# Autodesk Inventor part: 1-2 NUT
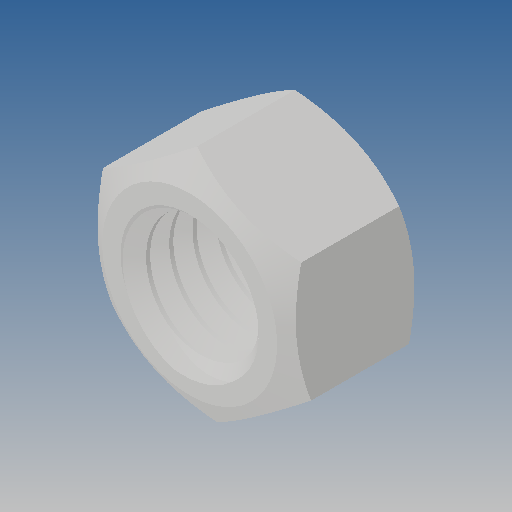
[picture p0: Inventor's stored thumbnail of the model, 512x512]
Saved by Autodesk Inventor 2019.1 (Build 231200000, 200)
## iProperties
Created: 2012-10
Part Number: 1-2 NUT
Material: Ogólny
Document SubType Name: Modeling
Designer: CADENGINEERING4
Density: 1 g/cm^3
Appearance: Domyślna
Author: CADENGINEERING4
Revision Number: ÈÎºÎ
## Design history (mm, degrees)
feature "ÇÐ³ý-É¨Ãè1"
node "Bryła1"
